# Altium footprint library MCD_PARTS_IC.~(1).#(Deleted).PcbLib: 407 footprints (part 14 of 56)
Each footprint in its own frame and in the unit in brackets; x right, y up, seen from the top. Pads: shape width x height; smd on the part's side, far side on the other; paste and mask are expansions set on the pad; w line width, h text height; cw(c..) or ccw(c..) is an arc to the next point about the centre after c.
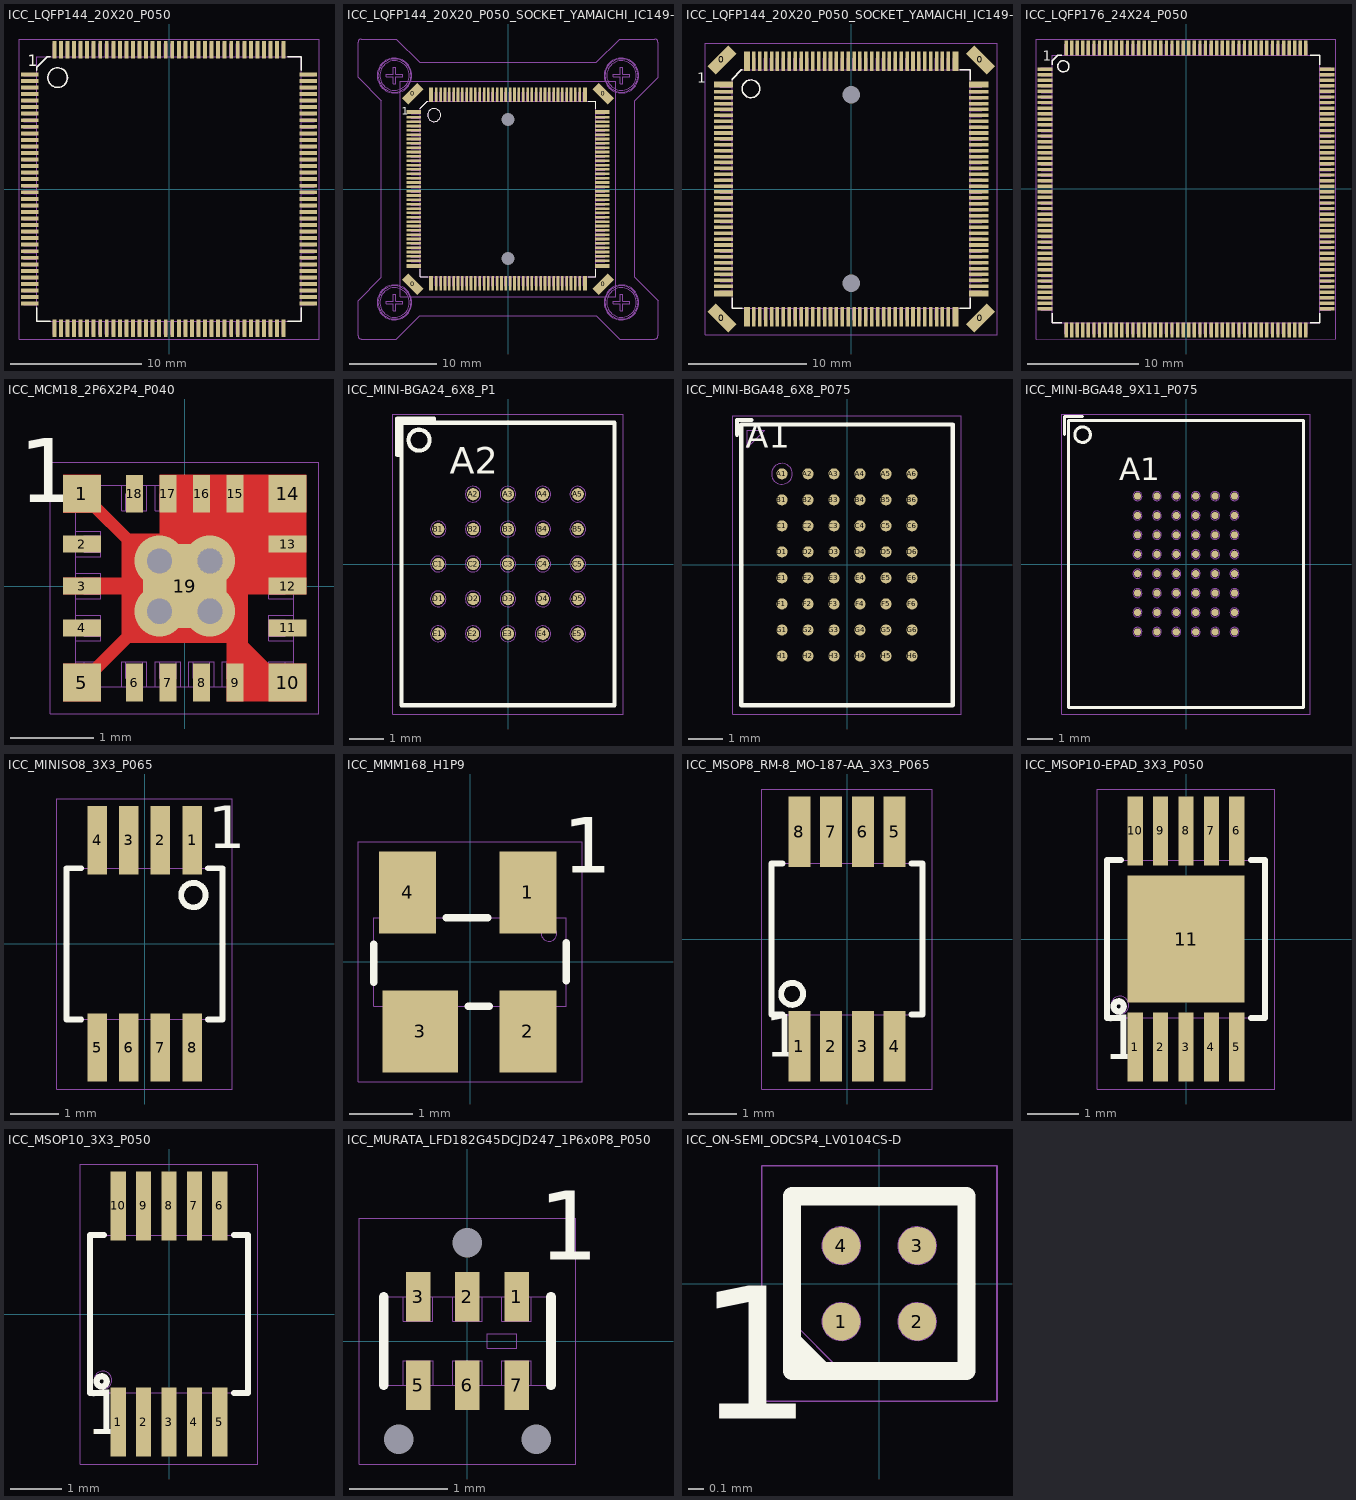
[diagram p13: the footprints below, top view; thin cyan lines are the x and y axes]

## ICC_LQFP144_20X20_P050 [mm]
height 1.6
pads (144):
  rect 1.35x0.3 smd mask+0.05: 1(-10.625,8.75) 2(-10.625,8.25) 3(-10.625,7.75) 4(-10.625,7.25) 5(-10.625,6.75) 6(-10.625,6.25) 7(-10.625,5.75) 8(-10.625,5.25) 9(-10.625,4.75) 10(-10.625,4.25) 11(-10.625,3.75) 12(-10.625,3.25) 13(-10.625,2.75) 14(-10.625,2.25) 15(-10.625,1.75) 16(-10.625,1.25) 17(-10.625,0.75) 18(-10.625,0.25) 19(-10.625,-0.25) 20(-10.625,-0.75) 21(-10.625,-1.25) 22(-10.625,-1.75) 23(-10.625,-2.25) 24(-10.625,-2.75) 25(-10.625,-3.25) 26(-10.625,-3.75) 27(-10.625,-4.25) 28(-10.625,-4.75) 29(-10.625,-5.25) 30(-10.625,-5.75) 31(-10.625,-6.25) 32(-10.625,-6.75) 33(-10.625,-7.25) 34(-10.625,-7.75) 35(-10.625,-8.25) 36(-10.625,-8.75) 73(10.625,-8.75) 74(10.625,-8.25) 75(10.625,-7.75) 76(10.625,-7.25) 77(10.625,-6.75) 78(10.625,-6.25) 79(10.625,-5.75) 80(10.625,-5.25) 81(10.625,-4.75) 82(10.625,-4.25) 83(10.625,-3.75) 84(10.625,-3.25) 85(10.625,-2.75) 86(10.625,-2.25) 87(10.625,-1.75) 88(10.625,-1.25) 89(10.625,-0.75) 90(10.625,-0.25) 91(10.625,0.25) 92(10.625,0.75) 93(10.625,1.25) 94(10.625,1.75) 95(10.625,2.25) 96(10.625,2.75) 97(10.625,3.25) 98(10.625,3.75) 99(10.625,4.25) 100(10.625,4.75) 101(10.625,5.25) 102(10.625,5.75) 103(10.625,6.25) 104(10.625,6.75) 105(10.625,7.25) 106(10.625,7.75) 107(10.625,8.25) 108(10.625,8.75)
  rect 0.3x1.35 smd mask+0.05: 37(-8.75,-10.625) 38(-8.25,-10.625) 39(-7.75,-10.625) 40(-7.25,-10.625) 41(-6.75,-10.625) 42(-6.25,-10.625) 43(-5.75,-10.625) 44(-5.25,-10.625) 45(-4.75,-10.625) 46(-4.25,-10.625) 47(-3.75,-10.625) 48(-3.25,-10.625) 49(-2.75,-10.625) 50(-2.25,-10.625) 51(-1.75,-10.625) 52(-1.25,-10.625) 53(-0.75,-10.625) 54(-0.25,-10.625) 55(0.25,-10.625) 56(0.75,-10.625) 57(1.25,-10.625) 58(1.75,-10.625) 59(2.25,-10.625) 60(2.75,-10.625) 61(3.25,-10.625) 62(3.75,-10.625) 63(4.25,-10.625) 64(4.75,-10.625) 65(5.25,-10.625) 66(5.75,-10.625) 67(6.25,-10.625) 68(6.75,-10.625) 69(7.25,-10.625) 70(7.75,-10.625) 71(8.25,-10.625) 72(8.75,-10.625) 109(8.75,10.625) 110(8.25,10.625) 111(7.75,10.625) 112(7.25,10.625) 113(6.75,10.625) 114(6.25,10.625) 115(5.75,10.625) 116(5.25,10.625) 117(4.75,10.625) 118(4.25,10.625) 119(3.75,10.625) 120(3.25,10.625) 121(2.75,10.625) 122(2.25,10.625) 123(1.75,10.625) 124(1.25,10.625) 125(0.75,10.625) 126(0.25,10.625) 127(-0.25,10.625) 128(-0.75,10.625) 129(-1.25,10.625) 130(-1.75,10.625) 131(-2.25,10.625) 132(-2.75,10.625) 133(-3.25,10.625) 134(-3.75,10.625) 135(-4.25,10.625) 136(-4.75,10.625) 137(-5.25,10.625) 138(-5.75,10.625) 139(-6.25,10.625) 140(-6.75,10.625) 141(-7.25,10.625) 142(-7.75,10.625) 143(-8.25,10.625) 144(-8.75,10.625)
Top Overlay:
  circle w0.12: c-8.5,8.5 r0.75
  lines w0.12: -10.1,-9.05 -10.1,-10.1 -9.05,-10.1 ; -10.1,9.05 -10.1,9.3 -9.3,10.1 -9.05,10.1 ; 9.05,-10.1 10.1,-10.1 10.1,-9.05 ; 9.05,10.1 10.1,10.1 10.1,9.05
  text "1" at -10.775,9.05 h1.5
M14-Top Assembly:
  drawing of 437 lines, arcs and shapes, not listed
  text "36" at -10,-9.25 h1
  text "37" at -9.725,-10 h1
  text "72" at 7.85,-10.025 h1
  text "73" at 8.05,-9.25 h1
  text "1" at -9.85,8.425 h1
  text "144" at -9.475,9.05 h1
  text "109" at 7.425,9.05 h1
  text "108" at 7.975,8.25 h1
  text "'.Designator'" at -2,-0.5 h0.75
M16-Top Courtyard:
  lines w0.01: -11.45,-11.45 -10.05,-11.45 11.45,-11.45 11.45,11.45 -9.05,11.45 -11.45,11.45 -11.45,-11.45
3D body: height 1.6, standoff 0, extent -10.099,-10.099 10.099,10.099
3D body "LQFP144_20X20_P050.STEP": height 1.58, standoff -0.02, extent -11,-11 11,11

## ICC_LQFP144_20X20_P050_SOCKET_YAMAICHI_IC149-144-145-B5 [mm]
height 12.6
pads (150):
  rect 1x2.5 smd rot 45 mask+0.05: 0(-10.96,-10.96) 0(10.96,10.96)
  rect 1x2.5 smd rot 135 mask+0.05: 0(-10.96,10.96) 0(10.96,-10.96)
  round 0 hole 1.5 unplated mask+0.05: 0(0,-8) 0(0,8)
  rect 1.65x0.5 smd mask+0.05: 1(-10.825,8.85) 36(-10.825,-8.85) 73(10.825,-8.85) 108(10.825,8.85)
  rect 1.65x0.3 smd mask+0.05: 2(-10.825,8.25) 3(-10.825,7.75) 4(-10.825,7.25) 5(-10.825,6.75) 6(-10.825,6.25) 7(-10.825,5.75) 8(-10.825,5.25) 9(-10.825,4.75) 10(-10.825,4.25) 11(-10.825,3.75) 12(-10.825,3.25) 13(-10.825,2.75) 14(-10.825,2.25) 15(-10.825,1.75) 16(-10.825,1.25) 17(-10.825,0.75) 18(-10.825,0.25) 19(-10.825,-0.25) 20(-10.825,-0.75) 21(-10.825,-1.25) 22(-10.825,-1.75) 23(-10.825,-2.25) 24(-10.825,-2.75) 25(-10.825,-3.25) 26(-10.825,-3.75) 27(-10.825,-4.25) 28(-10.825,-4.75) 29(-10.825,-5.25) 30(-10.825,-5.75) 31(-10.825,-6.25) 32(-10.825,-6.75) 33(-10.825,-7.25) 34(-10.825,-7.75) 35(-10.825,-8.25) 74(10.825,-8.25) 75(10.825,-7.75) 76(10.825,-7.25) 77(10.825,-6.75) 78(10.825,-6.25) 79(10.825,-5.75) 80(10.825,-5.25) 81(10.825,-4.75) 82(10.825,-4.25) 83(10.825,-3.75) 84(10.825,-3.25) 85(10.825,-2.75) 86(10.825,-2.25) 87(10.825,-1.75) 88(10.825,-1.25) 89(10.825,-0.75) 90(10.825,-0.25) 91(10.825,0.25) 92(10.825,0.75) 93(10.825,1.25) 94(10.825,1.75) 95(10.825,2.25) 96(10.825,2.75) 97(10.825,3.25) 98(10.825,3.75) 99(10.825,4.25) 100(10.825,4.75) 101(10.825,5.25) 102(10.825,5.75) 103(10.825,6.25) 104(10.825,6.75) 105(10.825,7.25) 106(10.825,7.75) 107(10.825,8.25)
  rect 0.5x1.65 smd mask+0.05: 37(-8.85,-10.825) 72(8.85,-10.825) 109(8.85,10.825) 144(-8.85,10.825)
  rect 0.3x1.65 smd mask+0.05: 38(-8.25,-10.825) 39(-7.75,-10.825) 40(-7.25,-10.825) 41(-6.75,-10.825) 42(-6.25,-10.825) 43(-5.75,-10.825) 44(-5.25,-10.825) 45(-4.75,-10.825) 46(-4.25,-10.825) 47(-3.75,-10.825) 48(-3.25,-10.825) 49(-2.75,-10.825) 50(-2.25,-10.825) 51(-1.75,-10.825) 52(-1.25,-10.825) 53(-0.75,-10.825) 54(-0.25,-10.825) 55(0.25,-10.825) 56(0.75,-10.825) 57(1.25,-10.825) 58(1.75,-10.825) 59(2.25,-10.825) 60(2.75,-10.825) 61(3.25,-10.825) 62(3.75,-10.825) 63(4.25,-10.825) 64(4.75,-10.825) 65(5.25,-10.825) 66(5.75,-10.825) 67(6.25,-10.825) 68(6.75,-10.825) 69(7.25,-10.825) 70(7.75,-10.825) 71(8.25,-10.825) 110(8.25,10.825) 111(7.75,10.825) 112(7.25,10.825) 113(6.75,10.825) 114(6.25,10.825) 115(5.75,10.825) 116(5.25,10.825) 117(4.75,10.825) 118(4.25,10.825) 119(3.75,10.825) 120(3.25,10.825) 121(2.75,10.825) 122(2.25,10.825) 123(1.75,10.825) 124(1.25,10.825) 125(0.75,10.825) 126(0.25,10.825) 127(-0.25,10.825) 128(-0.75,10.825) 129(-1.25,10.825) 130(-1.75,10.825) 131(-2.25,10.825) 132(-2.75,10.825) 133(-3.25,10.825) 134(-3.75,10.825) 135(-4.25,10.825) 136(-4.75,10.825) 137(-5.25,10.825) 138(-5.75,10.825) 139(-6.25,10.825) 140(-6.75,10.825) 141(-7.25,10.825) 142(-7.75,10.825) 143(-8.25,10.825)
Top Overlay:
  circle w0.12: c-8.5,8.5 r0.75
  lines w0.12: -10.1,-9.225 -10.1,-10.1 -9.225,-10.1 ; -10.1,9.225 -10.1,9.3 -9.3,10.1 -9.225,10.1 ; 9.225,-10.1 10.1,-10.1 10.1,-9.225 ; 9.225,10.1 10.1,10.1 10.1,9.225
  text "1" at -12.225,8.225 h1.5
M14-Top Assembly:
  drawing of 538 lines, arcs and shapes, not listed
  text "36" at -10,-9.25 h1
  text "37" at -9.725,-10 h1
  text "72" at 7.85,-10.025 h1
  text "73" at 8.05,-9.25 h1
  text "1" at -9.85,8.425 h1
  text "144" at -9.475,9.05 h1
  text "109" at 7.425,9.05 h1
  text "108" at 7.975,8.25 h1
  text "'.Designator'" at -2,-0.5 h0.75
M16-Top Courtyard:
  lines w0.01: -12.375,-12.375 -10.65,-12.375 12.375,-12.375 12.375,12.375 -8.125,12.375 -12.375,12.375 -12.375,-12.375
3D body: height 12.61, standoff 12.6, extent -15.05,-15.05 -11.05,-11.05
3D body: height 12.61, standoff 12.6, extent 11.05,-15.05 15.05,-11.05
3D body: height 12.61, standoff 12.6, extent 11.05,11.05 15.05,15.05
3D body: height 12.61, standoff 12.6, extent -15.05,11.05 -11.05,15.05
3D body: height 12.6, standoff 3.5, extent 10.5,-10.15 14.55,10.15
3D body: height 12.6, standoff 3.5, extent -10.15,10.5 10.15,14.55
3D body: height 12.6, standoff 3.5, extent -14.55,-10.15 -10.5,10.15
3D body: height 12.6, standoff 3.5, extent -10.15,-14.55 10.15,-10.5
3D body: height 3.5, standoff 0, extent -12.188,-12.187 -9.75,-9.75
3D body: height 3.5, standoff 0, extent 9.738,-12.175 12.175,-9.737
3D body: height 3.5, standoff 0, extent 9.744,9.744 12.181,12.181
3D body: height 3.5, standoff 0, extent -12.175,9.737 -9.738,12.175
3D body: height 3.5, standoff 0, extent -10.5,-10.5 10.5,10.5
3D body "LQFP144_20X20_P050.STEP": height 4.97, standoff 3.37, extent -11,-11 11,11
3D body: height 12.6, standoff 3.5, extent -17.25,10.15 -10.15,17.25
3D body: height 12.6, standoff 3.5, extent 10.15,10.15 17.25,17.25
3D body: height 12.6, standoff 3.5, extent 10.15,-17.25 17.25,-10.15
3D body: height 12.6, standoff 3.5, extent -17.25,-17.25 -10.15,-10.15
3D body: height 0.2, standoff 0, extent -11.1,8.65 -10.5,8.85
3D body: height 0.2, standoff 0, extent -11.1,8.15 -10.5,8.35
3D body: height 0.2, standoff 0, extent -11.1,7.65 -10.5,7.85
3D body: height 0.2, standoff 0, extent -11.1,7.15 -10.5,7.35
3D body: height 0.2, standoff 0, extent -11.1,6.65 -10.5,6.85
3D body: height 0.2, standoff 0, extent -11.1,6.15 -10.5,6.35
3D body: height 0.2, standoff 0, extent -11.1,3.15 -10.5,3.35
3D body: height 0.2, standoff 0, extent -11.1,3.65 -10.5,3.85
3D body: height 0.2, standoff 0, extent -11.1,4.15 -10.5,4.35
3D body: height 0.2, standoff 0, extent -11.1,4.65 -10.5,4.85
3D body: height 0.2, standoff 0, extent -11.1,5.15 -10.5,5.35
3D body: height 0.2, standoff 0, extent -11.1,5.65 -10.5,5.85
3D body: height 0.2, standoff 0, extent -11.1,0.15 -10.5,0.35
3D body: height 0.2, standoff 0, extent -11.1,0.65 -10.5,0.85
3D body: height 0.2, standoff 0, extent -11.1,1.15 -10.5,1.35
3D body: height 0.2, standoff 0, extent -11.1,1.65 -10.5,1.85
3D body: height 0.2, standoff 0, extent -11.1,2.15 -10.5,2.35
3D body: height 0.2, standoff 0, extent -11.1,2.65 -10.5,2.85
3D body: height 0.2, standoff 0, extent -11.1,-0.35 -10.5,-0.15
3D body: height 0.2, standoff 0, extent -11.1,-0.85 -10.5,-0.65
3D body: height 0.2, standoff 0, extent -11.1,-1.35 -10.5,-1.15
3D body: height 0.2, standoff 0, extent -11.1,-1.85 -10.5,-1.65
3D body: height 0.2, standoff 0, extent -11.1,-2.35 -10.5,-2.15
3D body: height 0.2, standoff 0, extent -11.1,-2.85 -10.5,-2.65
3D body: height 0.2, standoff 0, extent -11.1,-5.85 -10.5,-5.65
3D body: height 0.2, standoff 0, extent -11.1,-5.35 -10.5,-5.15
3D body: height 0.2, standoff 0, extent -11.1,-4.85 -10.5,-4.65
3D body: height 0.2, standoff 0, extent -11.1,-4.35 -10.5,-4.15
3D body: height 0.2, standoff 0, extent -11.1,-3.85 -10.5,-3.65
3D body: height 0.2, standoff 0, extent -11.1,-3.35 -10.5,-3.15
3D body: height 0.2, standoff 0, extent -11.1,-6.35 -10.5,-6.15
3D body: height 0.2, standoff 0, extent -11.1,-6.85 -10.5,-6.65
3D body: height 0.2, standoff 0, extent -11.1,-7.35 -10.5,-7.15
3D body: height 0.2, standoff 0, extent -11.1,-7.85 -10.5,-7.65
3D body: height 0.2, standoff 0, extent -11.1,-8.35 -10.5,-8.15
3D body: height 0.2, standoff 0, extent -11.1,-8.85 -10.5,-8.65
3D body: height 0.2, standoff 0, extent 8.65,-11.1 8.85,-10.5
3D body: height 0.2, standoff 0, extent 8.15,-11.1 8.35,-10.5
3D body: height 0.2, standoff 0, extent 7.65,-11.1 7.85,-10.5
3D body: height 0.2, standoff 0, extent 7.15,-11.1 7.35,-10.5
3D body: height 0.2, standoff 0, extent 6.65,-11.1 6.85,-10.5
3D body: height 0.2, standoff 0, extent 6.15,-11.1 6.35,-10.5
3D body: height 0.2, standoff 0, extent 3.15,-11.1 3.35,-10.5
3D body: height 0.2, standoff 0, extent 3.65,-11.1 3.85,-10.5
3D body: height 0.2, standoff 0, extent 4.15,-11.1 4.35,-10.5
3D body: height 0.2, standoff 0, extent 4.65,-11.1 4.85,-10.5
3D body: height 0.2, standoff 0, extent 5.15,-11.1 5.35,-10.5
3D body: height 0.2, standoff 0, extent 5.65,-11.1 5.85,-10.5
3D body: height 0.2, standoff 0, extent 2.65,-11.1 2.85,-10.5
3D body: height 0.2, standoff 0, extent 2.15,-11.1 2.35,-10.5
3D body: height 0.2, standoff 0, extent 1.65,-11.1 1.85,-10.5
3D body: height 0.2, standoff 0, extent 1.15,-11.1 1.35,-10.5
3D body: height 0.2, standoff 0, extent 0.65,-11.1 0.85,-10.5
3D body: height 0.2, standoff 0, extent 0.15,-11.1 0.35,-10.5
3D body: height 0.2, standoff 0, extent -2.85,-11.1 -2.65,-10.5
3D body: height 0.2, standoff 0, extent -2.35,-11.1 -2.15,-10.5
3D body: height 0.2, standoff 0, extent -1.85,-11.1 -1.65,-10.5
3D body: height 0.2, standoff 0, extent -1.35,-11.1 -1.15,-10.5
3D body: height 0.2, standoff 0, extent -0.85,-11.1 -0.65,-10.5
3D body: height 0.2, standoff 0, extent -0.35,-11.1 -0.15,-10.5
3D body: height 0.2, standoff 0, extent -5.85,-11.1 -5.65,-10.5
3D body: height 0.2, standoff 0, extent -5.35,-11.1 -5.15,-10.5
3D body: height 0.2, standoff 0, extent -4.85,-11.1 -4.65,-10.5
3D body: height 0.2, standoff 0, extent -4.35,-11.1 -4.15,-10.5
3D body: height 0.2, standoff 0, extent -3.85,-11.1 -3.65,-10.5
3D body: height 0.2, standoff 0, extent -3.35,-11.1 -3.15,-10.5
3D body: height 0.2, standoff 0, extent -6.35,-11.1 -6.15,-10.5
3D body: height 0.2, standoff 0, extent -6.85,-11.1 -6.65,-10.5
3D body: height 0.2, standoff 0, extent -7.35,-11.1 -7.15,-10.5
3D body: height 0.2, standoff 0, extent -7.85,-11.1 -7.65,-10.5
3D body: height 0.2, standoff 0, extent -8.35,-11.1 -8.15,-10.5
3D body: height 0.2, standoff 0, extent -8.85,-11.1 -8.65,-10.5
3D body: height 0.2, standoff 0, extent 10.5,8.65 11.1,8.85
3D body: height 0.2, standoff 0, extent 10.5,8.15 11.1,8.35
3D body: height 0.2, standoff 0, extent 10.5,7.65 11.1,7.85
3D body: height 0.2, standoff 0, extent 10.5,7.15 11.1,7.35
3D body: height 0.2, standoff 0, extent 10.5,6.65 11.1,6.85
3D body: height 0.2, standoff 0, extent 10.5,6.15 11.1,6.35
3D body: height 0.2, standoff 0, extent 10.5,3.15 11.1,3.35
3D body: height 0.2, standoff 0, extent 10.5,3.65 11.1,3.85
3D body: height 0.2, standoff 0, extent 10.5,4.15 11.1,4.35
3D body: height 0.2, standoff 0, extent 10.5,4.65 11.1,4.85
3D body: height 0.2, standoff 0, extent 10.5,5.15 11.1,5.35
3D body: height 0.2, standoff 0, extent 10.5,5.65 11.1,5.85
3D body: height 0.2, standoff 0, extent 10.5,2.65 11.1,2.85
3D body: height 0.2, standoff 0, extent 10.5,2.15 11.1,2.35
3D body: height 0.2, standoff 0, extent 10.5,1.65 11.1,1.85
3D body: height 0.2, standoff 0, extent 10.5,1.15 11.1,1.35
3D body: height 0.2, standoff 0, extent 10.5,0.65 11.1,0.85
3D body: height 0.2, standoff 0, extent 10.5,0.15 11.1,0.35
3D body: height 0.2, standoff 0, extent 10.5,-2.85 11.1,-2.65
3D body: height 0.2, standoff 0, extent 10.5,-2.35 11.1,-2.15
3D body: height 0.2, standoff 0, extent 10.5,-1.85 11.1,-1.65
3D body: height 0.2, standoff 0, extent 10.5,-1.35 11.1,-1.15
3D body: height 0.2, standoff 0, extent 10.5,-0.85 11.1,-0.65
3D body: height 0.2, standoff 0, extent 10.5,-0.35 11.1,-0.15
3D body: height 0.2, standoff 0, extent 10.5,-5.85 11.1,-5.65
3D body: height 0.2, standoff 0, extent 10.5,-5.35 11.1,-5.15
3D body: height 0.2, standoff 0, extent 10.5,-4.85 11.1,-4.65
3D body: height 0.2, standoff 0, extent 10.5,-4.35 11.1,-4.15
3D body: height 0.2, standoff 0, extent 10.5,-3.85 11.1,-3.65
3D body: height 0.2, standoff 0, extent 10.5,-3.35 11.1,-3.15
3D body: height 0.2, standoff 0, extent 10.5,-6.35 11.1,-6.15
3D body: height 0.2, standoff 0, extent 10.5,-6.85 11.1,-6.65
3D body: height 0.2, standoff 0, extent 10.5,-7.35 11.1,-7.15
3D body: height 0.2, standoff 0, extent 10.5,-7.85 11.1,-7.65
3D body: height 0.2, standoff 0, extent 10.5,-8.35 11.1,-8.15
3D body: height 0.2, standoff 0, extent 10.5,-8.85 11.1,-8.65
3D body: height 0.2, standoff 0, extent -8.85,10.5 -8.65,11.1
3D body: height 0.2, standoff 0, extent -8.35,10.5 -8.15,11.1
3D body: height 0.2, standoff 0, extent -7.85,10.5 -7.65,11.1
3D body: height 0.2, standoff 0, extent -7.35,10.5 -7.15,11.1
3D body: height 0.2, standoff 0, extent -6.85,10.5 -6.65,11.1
3D body: height 0.2, standoff 0, extent -6.35,10.5 -6.15,11.1
3D body: height 0.2, standoff 0, extent -3.35,10.5 -3.15,11.1
3D body: height 0.2, standoff 0, extent -3.85,10.5 -3.65,11.1
3D body: height 0.2, standoff 0, extent -4.35,10.5 -4.15,11.1
3D body: height 0.2, standoff 0, extent -4.85,10.5 -4.65,11.1
3D body: height 0.2, standoff 0, extent -5.35,10.5 -5.15,11.1
3D body: height 0.2, standoff 0, extent -5.85,10.5 -5.65,11.1
3D body: height 0.2, standoff 0, extent -2.85,10.5 -2.65,11.1
3D body: height 0.2, standoff 0, extent -2.35,10.5 -2.15,11.1
3D body: height 0.2, standoff 0, extent -1.85,10.5 -1.65,11.1
3D body: height 0.2, standoff 0, extent -1.35,10.5 -1.15,11.1
3D body: height 0.2, standoff 0, extent -0.85,10.5 -0.65,11.1
3D body: height 0.2, standoff 0, extent -0.35,10.5 -0.15,11.1
3D body: height 0.2, standoff 0, extent 2.65,10.5 2.85,11.1
3D body: height 0.2, standoff 0, extent 2.15,10.5 2.35,11.1
3D body: height 0.2, standoff 0, extent 1.65,10.5 1.85,11.1
3D body: height 0.2, standoff 0, extent 1.15,10.5 1.35,11.1
3D body: height 0.2, standoff 0, extent 0.65,10.5 0.85,11.1
3D body: height 0.2, standoff 0, extent 0.15,10.5 0.35,11.1
3D body: height 0.2, standoff 0, extent 5.65,10.5 5.85,11.1
3D body: height 0.2, standoff 0, extent 5.15,10.5 5.35,11.1
3D body: height 0.2, standoff 0, extent 4.65,10.5 4.85,11.1
3D body: height 0.2, standoff 0, extent 4.15,10.5 4.35,11.1
3D body: height 0.2, standoff 0, extent 3.65,10.5 3.85,11.1
3D body: height 0.2, standoff 0, extent 3.15,10.5 3.35,11.1
3D body: height 0.2, standoff 0, extent 6.15,10.5 6.35,11.1
3D body: height 0.2, standoff 0, extent 6.65,10.5 6.85,11.1
3D body: height 0.2, standoff 0, extent 7.15,10.5 7.35,11.1
3D body: height 0.2, standoff 0, extent 7.65,10.5 7.85,11.1
3D body: height 0.2, standoff 0, extent 8.15,10.5 8.35,11.1
3D body: height 0.2, standoff 0, extent 8.65,10.5 8.85,11.1

## ICC_LQFP144_20X20_P050_SOCKET_YAMAICHI_IC149-144-145-B5_NM [mm]
height 1.6
pads (150):
  rect 1x2.5 smd rot 45 mask+0.05: 0(-10.96,-10.96) 0(10.96,10.96)
  rect 1x2.5 smd rot 135 mask+0.05: 0(-10.96,10.96) 0(10.96,-10.96)
  round 0 hole 1.5 unplated mask+0.05: 0(0,-8) 0(0,8)
  rect 1.65x0.5 smd mask+0.05: 1(-10.825,8.85) 36(-10.825,-8.85) 73(10.825,-8.85) 108(10.825,8.85)
  rect 1.65x0.3 smd mask+0.05: 2(-10.825,8.25) 3(-10.825,7.75) 4(-10.825,7.25) 5(-10.825,6.75) 6(-10.825,6.25) 7(-10.825,5.75) 8(-10.825,5.25) 9(-10.825,4.75) 10(-10.825,4.25) 11(-10.825,3.75) 12(-10.825,3.25) 13(-10.825,2.75) 14(-10.825,2.25) 15(-10.825,1.75) 16(-10.825,1.25) 17(-10.825,0.75) 18(-10.825,0.25) 19(-10.825,-0.25) 20(-10.825,-0.75) 21(-10.825,-1.25) 22(-10.825,-1.75) 23(-10.825,-2.25) 24(-10.825,-2.75) 25(-10.825,-3.25) 26(-10.825,-3.75) 27(-10.825,-4.25) 28(-10.825,-4.75) 29(-10.825,-5.25) 30(-10.825,-5.75) 31(-10.825,-6.25) 32(-10.825,-6.75) 33(-10.825,-7.25) 34(-10.825,-7.75) 35(-10.825,-8.25) 74(10.825,-8.25) 75(10.825,-7.75) 76(10.825,-7.25) 77(10.825,-6.75) 78(10.825,-6.25) 79(10.825,-5.75) 80(10.825,-5.25) 81(10.825,-4.75) 82(10.825,-4.25) 83(10.825,-3.75) 84(10.825,-3.25) 85(10.825,-2.75) 86(10.825,-2.25) 87(10.825,-1.75) 88(10.825,-1.25) 89(10.825,-0.75) 90(10.825,-0.25) 91(10.825,0.25) 92(10.825,0.75) 93(10.825,1.25) 94(10.825,1.75) 95(10.825,2.25) 96(10.825,2.75) 97(10.825,3.25) 98(10.825,3.75) 99(10.825,4.25) 100(10.825,4.75) 101(10.825,5.25) 102(10.825,5.75) 103(10.825,6.25) 104(10.825,6.75) 105(10.825,7.25) 106(10.825,7.75) 107(10.825,8.25)
  rect 0.5x1.65 smd mask+0.05: 37(-8.85,-10.825) 72(8.85,-10.825) 109(8.85,10.825) 144(-8.85,10.825)
  rect 0.3x1.65 smd mask+0.05: 38(-8.25,-10.825) 39(-7.75,-10.825) 40(-7.25,-10.825) 41(-6.75,-10.825) 42(-6.25,-10.825) 43(-5.75,-10.825) 44(-5.25,-10.825) 45(-4.75,-10.825) 46(-4.25,-10.825) 47(-3.75,-10.825) 48(-3.25,-10.825) 49(-2.75,-10.825) 50(-2.25,-10.825) 51(-1.75,-10.825) 52(-1.25,-10.825) 53(-0.75,-10.825) 54(-0.25,-10.825) 55(0.25,-10.825) 56(0.75,-10.825) 57(1.25,-10.825) 58(1.75,-10.825) 59(2.25,-10.825) 60(2.75,-10.825) 61(3.25,-10.825) 62(3.75,-10.825) 63(4.25,-10.825) 64(4.75,-10.825) 65(5.25,-10.825) 66(5.75,-10.825) 67(6.25,-10.825) 68(6.75,-10.825) 69(7.25,-10.825) 70(7.75,-10.825) 71(8.25,-10.825) 110(8.25,10.825) 111(7.75,10.825) 112(7.25,10.825) 113(6.75,10.825) 114(6.25,10.825) 115(5.75,10.825) 116(5.25,10.825) 117(4.75,10.825) 118(4.25,10.825) 119(3.75,10.825) 120(3.25,10.825) 121(2.75,10.825) 122(2.25,10.825) 123(1.75,10.825) 124(1.25,10.825) 125(0.75,10.825) 126(0.25,10.825) 127(-0.25,10.825) 128(-0.75,10.825) 129(-1.25,10.825) 130(-1.75,10.825) 131(-2.25,10.825) 132(-2.75,10.825) 133(-3.25,10.825) 134(-3.75,10.825) 135(-4.25,10.825) 136(-4.75,10.825) 137(-5.25,10.825) 138(-5.75,10.825) 139(-6.25,10.825) 140(-6.75,10.825) 141(-7.25,10.825) 142(-7.75,10.825) 143(-8.25,10.825)
Top Overlay:
  circle w0.12: c-8.5,8.5 r0.75
  lines w0.12: -10.1,-9.225 -10.1,-10.1 -9.225,-10.1 ; -10.1,9.225 -10.1,9.3 -9.3,10.1 -9.225,10.1 ; 9.225,-10.1 10.1,-10.1 10.1,-9.225 ; 9.225,10.1 10.1,10.1 10.1,9.225
  text "1" at -13.075,8.725 h1.5
M14-Top Assembly:
  drawing of 438 lines, arcs and shapes, not listed
  text "36" at -9.8,-9.05 h1
  text "37" at -9.775,-9.85 h1
  text "72" at 7.825,-9.825 h1
  text "73" at 7.775,-9.175 h1
  text "1" at -9.85,8.425 h1
  text "144" at -9.225,8.825 h1
  text "109" at 7.2,8.725 h1
  text "108" at 7.85,8 h1
  text "'.Designator'" at -2,-0.5 h0.75
M16-Top Courtyard:
  lines w0.01: -12.375,-12.375 -10.65,-12.375 12.375,-12.375 12.375,12.375 -8.125,12.375 -12.375,12.375 -12.375,-12.375
3D body "LQFP144_20X20_P050.STEP": height 1.6, standoff 0, extent -11,-11 11,11

## ICC_LQFP176_24X24_P050 [mm] "MCD-04398"
height 1.6
pads (176):
  rect 1.35x0.3 smd mask+0.05: 1(-12.625,10.75) 2(-12.625,10.25) 3(-12.625,9.75) 4(-12.625,9.25) 5(-12.625,8.75) 6(-12.625,8.25) 7(-12.625,7.75) 8(-12.625,7.25) 9(-12.625,6.75) 10(-12.625,6.25) 11(-12.625,5.75) 12(-12.625,5.25) 13(-12.625,4.75) 14(-12.625,4.25) 15(-12.625,3.75) 16(-12.625,3.25) 17(-12.625,2.75) 18(-12.625,2.25) 19(-12.625,1.75) 20(-12.625,1.25) 21(-12.625,0.75) 22(-12.625,0.25) 23(-12.625,-0.25) 24(-12.625,-0.75) 25(-12.625,-1.25) 26(-12.625,-1.75) 27(-12.625,-2.25) 28(-12.625,-2.75) 29(-12.625,-3.25) 30(-12.625,-3.75) 31(-12.625,-4.25) 32(-12.625,-4.75) 33(-12.625,-5.25) 34(-12.625,-5.75) 35(-12.625,-6.25) 36(-12.625,-6.75) 37(-12.625,-7.25) 38(-12.625,-7.75) 39(-12.625,-8.25) 40(-12.625,-8.75) 41(-12.625,-9.25) 42(-12.625,-9.75) 43(-12.625,-10.25) 44(-12.625,-10.75) 89(12.625,-10.75) 90(12.625,-10.25) 91(12.625,-9.75) 92(12.625,-9.25) 93(12.625,-8.75) 94(12.625,-8.25) 95(12.625,-7.75) 96(12.625,-7.25) 97(12.625,-6.75) 98(12.625,-6.25) 99(12.625,-5.75) 100(12.625,-5.25) 101(12.625,-4.75) 102(12.625,-4.25) 103(12.625,-3.75) 104(12.625,-3.25) 105(12.625,-2.75) 106(12.625,-2.25) 107(12.625,-1.75) 108(12.625,-1.25) 109(12.625,-0.75) 110(12.625,-0.25) 111(12.625,0.25) 112(12.625,0.75) 113(12.625,1.25) 114(12.625,1.75) 115(12.625,2.25) 116(12.625,2.75) 117(12.625,3.25) 118(12.625,3.75) 119(12.625,4.25) 120(12.625,4.75) 121(12.625,5.25) 122(12.625,5.75) 123(12.625,6.25) 124(12.625,6.75) 125(12.625,7.25) 126(12.625,7.75) 127(12.625,8.25) 128(12.625,8.75) 129(12.625,9.25) 130(12.625,9.75) 131(12.625,10.25) 132(12.625,10.75)
  rect 0.3x1.35 smd mask+0.05: 45(-10.75,-12.625) 46(-10.25,-12.625) 47(-9.75,-12.625) 48(-9.25,-12.625) 49(-8.75,-12.625) 50(-8.25,-12.625) 51(-7.75,-12.625) 52(-7.25,-12.625) 53(-6.75,-12.625) 54(-6.25,-12.625) 55(-5.75,-12.625) 56(-5.25,-12.625) 57(-4.75,-12.625) 58(-4.25,-12.625) 59(-3.75,-12.625) 60(-3.25,-12.625) 61(-2.75,-12.625) 62(-2.25,-12.625) 63(-1.75,-12.625) 64(-1.25,-12.625) 65(-0.75,-12.625) 66(-0.25,-12.625) 67(0.25,-12.625) 68(0.75,-12.625) 69(1.25,-12.625) 70(1.75,-12.625) 71(2.25,-12.625) 72(2.75,-12.625) 73(3.25,-12.625) 74(3.75,-12.625) 75(4.25,-12.625) 76(4.75,-12.625) 77(5.25,-12.625) 78(5.75,-12.625) 79(6.25,-12.625) 80(6.75,-12.625) 81(7.25,-12.625) 82(7.75,-12.625) 83(8.25,-12.625) 84(8.75,-12.625) 85(9.25,-12.625) 86(9.75,-12.625) 87(10.25,-12.625) 88(10.75,-12.625) 133(10.75,12.625) 134(10.25,12.625) 135(9.75,12.625) 136(9.25,12.625) 137(8.75,12.625) 138(8.25,12.625) 139(7.75,12.625) 140(7.25,12.625) 141(6.75,12.625) 142(6.25,12.625) 143(5.75,12.625) 144(5.25,12.625) 145(4.75,12.625) 146(4.25,12.625) 147(3.75,12.625) 148(3.25,12.625) 149(2.75,12.625) 150(2.25,12.625) 151(1.75,12.625) 152(1.25,12.625) 153(0.75,12.625) 154(0.25,12.625) 155(-0.25,12.625) 156(-0.75,12.625) 157(-1.25,12.625) 158(-1.75,12.625) 159(-2.25,12.625) 160(-2.75,12.625) 161(-3.25,12.625) 162(-3.75,12.625) 163(-4.25,12.625) 164(-4.75,12.625) 165(-5.25,12.625) 166(-5.75,12.625) 167(-6.25,12.625) 168(-6.75,12.625) 169(-7.25,12.625) 170(-7.75,12.625) 171(-8.25,12.625) 172(-8.75,12.625) 173(-9.25,12.625) 174(-9.75,12.625) 175(-10.25,12.625) 176(-10.75,12.625)
Top Overlay:
  circle w0.12: c-11,11 r0.5
  lines w0.12: -12,-11.127 -12,-12 -11.125,-12 ; -12,11.125 -12,11.5 -11.5,12 -11.125,12 ; 11.125,12 12,12 12,11.127 ; 11.127,-12 12,-12 12,-11.125
  text "1" at -12.85,11.175 h1.5
M14-Top Assembly:
  drawing of 533 lines, arcs and shapes, not listed
  text "44" at -12.975,-11.125 h1
  text "88" at 9.8,-12.85 h1
  text "45" at -11.8,-12.825 h1
  text "176" at -12.05,12 h1
  text "1" at -12.625,10.45 h1
  text "132" at 11.85,10.175 h1
  text "133" at 8.625,11.85 h1
  text "89" at 11.025,-11.275 h1
  text "'.Designator'" at -2,-0.5 h0.75
M16-Top Courtyard:
  lines w0.01: -13.45,-13.45 13.45,-13.45 13.45,13.45 -13.45,13.45 -13.45,-13.45
3D body "User Library-LQFP176-0_5.STEP": height 1.6, standoff 0.03, extent -12.886,-12.886 12.886,12.886

## ICC_MCM18_2P6X2P4_P040 [mm]
height 0.8
pads (19):
  rect 0.45x0.45 smd mask+0.05: 1(-1.225,1.1) 5(-1.225,-1.15) 10(1.225,-1.15) 14(1.225,1.1)
  rect 0.45x0.2 smd mask+0.05: 2(-1.225,0.5) 3(-1.225,0) 4(-1.225,-0.5) 11(1.225,-0.5) 12(1.225,0) 13(1.225,0.5)
  rect 0.2x0.45 smd mask+0.05: 6(-0.6,-1.15) 7(-0.2,-1.15) 8(0.2,-1.15) 9(0.6,-1.15) 15(0.6,1.1) 16(0.2,1.1) 17(-0.2,1.1) 18(-0.6,1.1)
  rect 1x1 smd mask+0.05: 19(0,0)
via 0.3,0.3 diameter 0.6 hole 0.3
via 0.3,-0.3 diameter 0.6 hole 0.3
via -0.3,-0.3 diameter 0.6 hole 0.3
via -0.3,0.3 diameter 0.6 hole 0.3
Top Layer:
  region: -0.3,0.625 -0.65,0.625 -1,0.975 -1,1.325 -1.45,1.325 -1.45,0.875 -1.1,0.875 -0.75,0.525 -0.75,0.1 -1.45,0.1 -1.45,-0.1 -0.75,-0.1 -0.75,-0.575 -1.1,-0.925 -1.45,-0.925 -1.45,-1.375 -1,-1.375 -1,-1.05 -1,-1.025 -0.65,-0.675 0.5,-0.675 0.5,-1.375 1.45,-1.375 1.45,-0.925 1,-0.925 0.75,-0.675 0.75,-0.1 1.45,-0.1 1.45,1.325 -0.3,1.325
Top Overlay:
  text "1" at -1.975,0.75 h1.3
M14-Top Assembly:
  lines w0.01: -1.3,-0.9 -1,-0.9 -1,-1.2 ; -1.3,-0.65 -1,-0.65 -1,-0.35 -1.3,-0.35 ; -1.3,-0.15 -1,-0.15 -1,0.15 -1.3,0.15 ; -1.3,0.35 -1,0.35 -1,0.65 -1.3,0.65 ; -1.3,0.9 -1,0.9 -1,1.2 ; -1.2,-0.9 -1.2,-1.1 -1,-1.1 ; -1.2,0.9 -1.2,1.1 -1,1.1 ; -1,-0.6 -1.2,-0.6 -1.2,-0.4 -1,-0.4 ; -1,-0.1 -1.2,-0.1 -1.2,0.1 -1,0.1 ; -1,0.4 -1.2,0.4 -1.2,0.6 -1,0.6 ; -0.75,-1.2 -0.75,-0.9 -0.45,-0.9 -0.45,-1.2 ; -0.75,1.2 -0.75,0.9 -0.45,0.9 -0.45,1.2 ; -0.7,-0.9 -0.7,-1.1 -0.5,-1.1 -0.5,-0.9 ; -0.7,0.9 -0.7,1.1 -0.5,1.1 -0.5,0.9 ; -0.35,-1.2 -0.35,-0.9 -0.05,-0.9 -0.05,-1.2 ; -0.35,1.2 -0.35,0.9 -0.05,0.9 -0.05,1.2 ; -0.3,-0.9 -0.3,-1.1 -0.1,-1.1 -0.1,-0.9 ; -0.3,0.9 -0.3,1.1 -0.1,1.1 -0.1,0.9 ; 0.05,-1.2 0.05,-0.9 0.35,-0.9 0.35,-1.2 ; 0.05,1.2 0.05,0.9 0.35,0.9 0.35,1.2 ; 0.1,-0.9 0.1,-1.1 0.3,-1.1 0.3,-0.9 ; 0.1,0.9 0.1,1.1 0.3,1.1 0.3,0.9 ; 0.45,-1.2 0.45,-0.9 0.75,-0.9 0.75,-1.2 ; 0.45,1.2 0.45,0.9 0.75,0.9 0.75,1.2 ; 0.5,-0.9 0.5,-1.1 0.7,-1.1 0.7,-0.9 ; 0.5,0.9 0.5,1.1 0.7,1.1 0.7,0.9 ; 1,-1.2 1,-0.9 1.3,-0.9 ; 1,-1.1 1.2,-1.1 1.2,-0.9 ; 1,-0.6 1.2,-0.6 1.2,-0.4 1,-0.4 ; 1,-0.1 1.2,-0.1 1.2,0.1 1,0.1 ; 1,0.4 1.2,0.4 1.2,0.6 1,0.6 ; 1,1.1 1.2,1.1 1.2,0.9 ; 1,1.2 1,0.9 1.3,0.9 ; 1.3,-0.65 1,-0.65 1,-0.35 1.3,-0.35 ; 1.3,-0.15 1,-0.15 1,0.15 1.3,0.15 ; 1.3,0.35 1,0.35 1,0.65 1.3,0.65 ; -1.3,-1.2 1.3,-1.2 1.3,1.2 -1.3,1.2 -1.3,-1.2 ; -0.5,-0.5 0.5,-0.5 0.5,0.5 -0.3,0.5 -0.5,0.3 -0.5,-0.5
  text "1" at -1.2,0.9 h0.5
  text "'.Designator'" at -2,-0.5 h0.75
  text "5" at -1.2,-1.2 h0.5
  text "10" at 0.925,-1.2 h0.5
  text "14" at 0.925,0.9 h0.5
M16-Top Courtyard:
  lines w0.01: -1.6,-1.525 1.6,-1.525 1.6,1.475 -1.6,1.475 -1.6,-1.525
3D body: height 0.8, standoff 0, extent -1.3,-1.2 1.3,1.2
3D body: height 0.81, standoff 0.8, extent -1.125,0.725 -0.825,1.025

## ICC_MINI-BGA24_6X8_P1 [mm] "MCD-01391"
height 1.2
pads (24):
  round 0.35 smd mask+0.05: A2(-1,2) A3(0,2) A4(1,2) A5(2,2) B1(-2,1) B2(-1,1) B3(0,1) B4(1,1) B5(2,1) C1(-2,0) C2(-1,0) C3(0,0) C4(1,0) C5(2,0) D1(-2,-1) D2(-1,-1) D3(0,-1) D4(1,-1) D5(2,-1) E1(-2,-2) E2(-1,-2) E3(0,-2) E4(1,-2) E5(2,-2)
Top Overlay:
  circle w0.12: c-2.55,3.55 r0.3
  lines w0.12: -3.15,3.125 -3.15,4.15 -2.125,4.15 ; -3.05,3.125 -3.175,3.125 -3.175,4.175 -2.125,4.175 -2.125,4.05 ; -3.05,-4.05 -3.05,4.05 3.05,4.05 3.05,-4.05 -3.05,-4.05
  text "A2" at -1.675,2.325 h1.3
M14-Top Assembly:
  circle w0.01: c-2,-2 r0.225
  circle w0.01: c-1,-2 r0.225
  circle w0.01: c0,-2 r0.225
  circle w0.01: c1,-2 r0.225
  circle w0.01: c2,-2 r0.225
  circle w0.01: c-2,-1 r0.225
  circle w0.01: c-1,-1 r0.225
  circle w0.01: c0,-1 r0.225
  circle w0.01: c1,-1 r0.225
  circle w0.01: c2,-1 r0.225
  circle w0.01: c-2,0 r0.225
  circle w0.01: c-1,0 r0.225
  circle w0.01: c0,0 r0.225
  circle w0.01: c1,0 r0.225
  circle w0.01: c2,0 r0.225
  circle w0.01: c-2,1 r0.225
  circle w0.01: c-1,1 r0.225
  circle w0.01: c0,1 r0.225
  circle w0.01: c1,1 r0.225
  circle w0.01: c2,1 r0.225
  circle w0.01: c2,2 r0.225
  circle w0.01: c1,2 r0.225
  circle w0.01: c0,2 r0.225
  circle w0.01: c-1,2 r0.225
  circle w0.01: c-2.55,3.55 r0.325
  lines w0.01: -3.05,-4.05 3.05,-4.05 3.05,4.05 -3.05,4.05 -3.05,-4.05
  text "A2" at -1.45,1.775 h0.75
  text "'.Designator'" at -2,0 h0.75
M16-Top Courtyard:
  lines w0.01: -3.3,-4.3 3.3,-4.3 3.3,4.3 -3.3,4.3 -3.3,-4.3
3D body: height 0.36, standoff -0.04, extent 1.801,-2.197 2.2,-1.803
3D body: height 0.36, standoff -0.04, extent 0.801,-2.197 1.2,-1.803
3D body: height 0.36, standoff -0.04, extent -0.199,-2.197 0.2,-1.803
3D body: height 0.36, standoff -0.04, extent -1.199,-2.197 -0.8,-1.803
3D body: height 0.36, standoff -0.04, extent -2.199,-2.197 -1.8,-1.803
3D body: height 0.36, standoff -0.04, extent 1.801,-1.197 2.2,-0.803
3D body: height 0.36, standoff -0.04, extent 0.801,-1.197 1.2,-0.803
3D body: height 0.36, standoff -0.04, extent -0.199,-1.197 0.2,-0.803
3D body: height 0.36, standoff -0.04, extent -1.199,-1.197 -0.8,-0.803
3D body: height 0.36, standoff -0.04, extent -2.199,-1.197 -1.8,-0.803
3D body: height 0.36, standoff -0.04, extent 1.801,-0.197 2.2,0.197
3D body: height 0.36, standoff -0.04, extent 0.801,-0.197 1.2,0.197
3D body: height 0.36, standoff -0.04, extent -0.199,-0.197 0.2,0.197
3D body: height 0.36, standoff -0.04, extent -1.199,-0.197 -0.8,0.197
3D body: height 0.36, standoff -0.04, extent -2.199,-0.197 -1.8,0.197
3D body: height 0.36, standoff -0.04, extent 1.801,0.803 2.2,1.197
3D body: height 0.36, standoff -0.04, extent 0.801,0.803 1.2,1.197
3D body: height 0.36, standoff -0.04, extent -0.199,0.803 0.2,1.197
3D body: height 0.36, standoff -0.04, extent -1.199,0.803 -0.8,1.197
3D body: height 0.36, standoff -0.04, extent -2.199,0.803 -1.8,1.197
3D body: height 0.36, standoff -0.04, extent 1.801,1.803 2.2,2.197
3D body: height 0.36, standoff -0.04, extent 0.801,1.803 1.2,2.197
3D body: height 0.36, standoff -0.04, extent -0.199,1.803 0.2,2.197
3D body: height 0.36, standoff -0.04, extent -1.199,1.803 -0.8,2.197
3D body: height 1.2, standoff 0.3, extent -3.055,-4.055 3.055,4.055
3D body: height 1.21, standoff 1.2, extent -2.623,3.026 -2.025,3.625

## ICC_MINI-BGA48_6X8_P075 [mm]
height 1.2
pads (48):
  round 0.32 smd mask+0.05: A1(-1.875,2.625) A2(-1.125,2.625) A3(-0.375,2.625) A4(0.375,2.625) A5(1.125,2.625) A6(1.875,2.625) B1(-1.875,1.875) B2(-1.125,1.875) B3(-0.375,1.875) B4(0.375,1.875) B5(1.125,1.875) B6(1.875,1.875) C1(-1.875,1.125) C2(-1.125,1.125) C3(-0.375,1.125) C4(0.375,1.125) C5(1.125,1.125) C6(1.875,1.125) D1(-1.875,0.375) D2(-1.125,0.375) D3(-0.375,0.375) D4(0.375,0.375) D5(1.125,0.375) D6(1.875,0.375) E1(-1.875,-0.375) E2(-1.125,-0.375) E3(-0.375,-0.375) E4(0.375,-0.375) E5(1.125,-0.375) E6(1.875,-0.375) F1(-1.875,-1.125) F2(-1.125,-1.125) F3(-0.375,-1.125) F4(0.375,-1.125) F5(1.125,-1.125) F6(1.875,-1.125) G1(-1.875,-1.875) G2(-1.125,-1.875) G3(-0.375,-1.875) G4(0.375,-1.875) G5(1.125,-1.875) G6(1.875,-1.875) H1(-1.875,-2.625) H2(-1.125,-2.625) H3(-0.375,-2.625) H4(0.375,-2.625) H5(1.125,-2.625) H6(1.875,-2.625)
Top Overlay:
  lines w0.12: -3.175,3.75 -3.175,4.175 -2.75,4.175 ; -3.05,-4.05 -3.05,4.05 3.05,4.05 3.05,-4.05 -3.05,-4.05
  text "A1" at -2.925,3.15 h1.2
M14-Top Assembly:
  circle w0.01: c-1.875,2.625 r0.3
  lines w0.01: -3.05,-4.05 3.05,-4.05 3.05,4.05 -3.05,4.05 -3.05,-4.05 ; -2.875,3.375 -2.875,3.5 -2.875,3.875 -2.375,3.875 -2.875,3.375
  text "'.Designator'" at -2,-0.5 h0.75
  text "A1" at -2.225,2.975 h0.75
M16-Top Courtyard:
  lines w0.01: -3.3,-4.3 3.3,-4.3 3.3,4.3 -3.3,4.3 -3.3,-4.3
3D body: height 1.2, standoff 0, extent -3.055,-4.055 3.055,4.055
3D body "MINI-BGA48_6X8.STEP": height 1.2, standoff 0, extent -3,-4 3,4

## ICC_MINI-BGA48_9X11_P075 [mm] "IPC"
height 1.2
pads (48):
  round 0.28 smd mask+0.05: A1(-1.875,2.625) A2(-1.125,2.625) A3(-0.375,2.625) A4(0.375,2.625) A5(1.125,2.625) A6(1.875,2.625) B1(-1.875,1.875) B2(-1.125,1.875) B3(-0.375,1.875) B4(0.375,1.875) B5(1.125,1.875) B6(1.875,1.875) C1(-1.875,1.125) C2(-1.125,1.125) C3(-0.375,1.125) C4(0.375,1.125) C5(1.125,1.125) C6(1.875,1.125) D1(-1.875,0.375) D2(-1.125,0.375) D3(-0.375,0.375) D4(0.375,0.375) D5(1.125,0.375) D6(1.875,0.375) E1(-1.875,-0.375) E2(-1.125,-0.375) E3(-0.375,-0.375) E4(0.375,-0.375) E5(1.125,-0.375) E6(1.875,-0.375) F1(-1.875,-1.125) F2(-1.125,-1.125) F3(-0.375,-1.125) F4(0.375,-1.125) F5(1.125,-1.125) F6(1.875,-1.125) G1(-1.875,-1.875) G2(-1.125,-1.875) G3(-0.375,-1.875) G4(0.375,-1.875) G5(1.125,-1.875) G6(1.875,-1.875) H1(-1.875,-2.625) H2(-1.125,-2.625) H3(-0.375,-2.625) H4(0.375,-2.625) H5(1.125,-2.625) H6(1.875,-2.625)
Top Overlay:
  circle w0.12: c-4,5 r0.3
  lines w0.12: -4.7,5 -4.7,5.7 -4,5.7 ; -4.55,-5.55 -4.55,5.55 4.55,5.55 4.55,-5.55 -4.55,-5.55
  text "A1" at -2.575,2.95 h1.5
M14-Top Assembly:
  circle w0.01: c-1.125,-2.625 r0.175
  circle w0.01: c-1.875,-2.625 r0.175
  circle w0.01: c-0.375,-2.625 r0.175
  circle w0.01: c0.375,-2.625 r0.175
  circle w0.01: c1.125,-2.625 r0.175
  circle w0.01: c1.875,-2.625 r0.175
  circle w0.01: c-1.125,-1.875 r0.175
  circle w0.01: c-1.875,-1.875 r0.175
  circle w0.01: c-0.375,-1.875 r0.175
  circle w0.01: c0.375,-1.875 r0.175
  circle w0.01: c1.125,-1.875 r0.175
  circle w0.01: c1.875,-1.875 r0.175
  circle w0.01: c-1.125,-1.125 r0.175
  circle w0.01: c-1.875,-1.125 r0.175
  circle w0.01: c-0.375,-1.125 r0.175
  circle w0.01: c0.375,-1.125 r0.175
  circle w0.01: c1.125,-1.125 r0.175
  circle w0.01: c1.875,-1.125 r0.175
  circle w0.01: c-1.125,-0.375 r0.175
  circle w0.01: c-1.875,-0.375 r0.175
  circle w0.01: c-0.375,-0.375 r0.175
  circle w0.01: c0.375,-0.375 r0.175
  circle w0.01: c1.125,-0.375 r0.175
  circle w0.01: c1.875,-0.375 r0.175
  circle w0.01: c-1.125,0.375 r0.175
  circle w0.01: c-1.875,0.375 r0.175
  circle w0.01: c-0.375,0.375 r0.175
  circle w0.01: c0.375,0.375 r0.175
  circle w0.01: c1.125,0.375 r0.175
  circle w0.01: c1.875,0.375 r0.175
  circle w0.01: c-1.125,1.125 r0.175
  circle w0.01: c-1.875,1.125 r0.175
  circle w0.01: c-0.375,1.125 r0.175
  circle w0.01: c0.375,1.125 r0.175
  circle w0.01: c1.125,1.125 r0.175
  circle w0.01: c1.875,1.125 r0.175
  circle w0.01: c-1.125,1.875 r0.175
  circle w0.01: c-1.875,1.875 r0.175
  circle w0.01: c-0.375,1.875 r0.175
  circle w0.01: c0.375,1.875 r0.175
  circle w0.01: c1.125,1.875 r0.175
  circle w0.01: c1.875,1.875 r0.175
  circle w0.01: c1.875,2.625 r0.175
  circle w0.01: c1.125,2.625 r0.175
  circle w0.01: c0.375,2.625 r0.175
  circle w0.01: c-0.375,2.625 r0.175
  circle w0.01: c-4,5 r0.3
  circle w0.01: c-1.875,2.625 r0.175
  circle w0.01: c-1.125,2.625 r0.175
  lines w0.01: -4.55,-5.55 4.55,-5.55 4.55,5.55 -4.55,5.55 -4.55,-5.55
  text "'.Designator'" at -2,-0.5 h0.75
  text "A1" at -2.125,2.475 h0.5
M16-Top Courtyard:
  lines w0.01: -4.8,-5.8 4.8,-5.8 4.8,5.8 -4.8,5.8 -4.8,-5.8
3D body: height 0.31, standoff -0.05, extent -2.041,2.458 -1.7,2.792
3D body: height 1.21, standoff 1.2, extent -4.248,4.75 -3.75,5.25
3D body: height 1.2, standoff 0.25, extent -4.55,-5.55 4.55,5.55
3D body: height 0.31, standoff -0.05, extent -1.291,2.458 -0.95,2.792
3D body: height 0.31, standoff -0.05, extent -0.541,2.458 -0.2,2.792
3D body: height 0.31, standoff -0.05, extent 0.209,2.458 0.55,2.792
3D body: height 0.31, standoff -0.05, extent 0.959,2.458 1.3,2.792
3D body: height 0.31, standoff -0.05, extent 1.709,2.458 2.05,2.792
3D body: height 0.31, standoff -0.05, extent 1.709,1.708 2.05,2.042
3D body: height 0.31, standoff -0.05, extent 0.959,1.708 1.3,2.042
3D body: height 0.31, standoff -0.05, extent 0.209,1.708 0.55,2.042
3D body: height 0.31, standoff -0.05, extent -0.541,1.708 -0.2,2.042
3D body: height 0.31, standoff -0.05, extent -1.291,1.708 -0.95,2.042
3D body: height 0.31, standoff -0.05, extent -2.041,1.708 -1.7,2.042
3D body: height 0.31, standoff -0.05, extent 1.709,0.958 2.05,1.292
3D body: height 0.31, standoff -0.05, extent 0.959,0.958 1.3,1.292
3D body: height 0.31, standoff -0.05, extent 0.209,0.958 0.55,1.292
3D body: height 0.31, standoff -0.05, extent -0.541,0.958 -0.2,1.292
3D body: height 0.31, standoff -0.05, extent -1.291,0.958 -0.95,1.292
3D body: height 0.31, standoff -0.05, extent -2.041,0.958 -1.7,1.292
3D body: height 0.31, standoff -0.05, extent 1.709,0.208 2.05,0.542
3D body: height 0.31, standoff -0.05, extent 0.959,0.208 1.3,0.542
3D body: height 0.31, standoff -0.05, extent 0.209,0.208 0.55,0.542
3D body: height 0.31, standoff -0.05, extent -0.541,0.208 -0.2,0.542
3D body: height 0.31, standoff -0.05, extent -1.291,0.208 -0.95,0.542
3D body: height 0.31, standoff -0.05, extent -2.041,0.208 -1.7,0.542
3D body: height 0.31, standoff -0.05, extent 1.709,-0.542 2.05,-0.208
3D body: height 0.31, standoff -0.05, extent 0.959,-0.542 1.3,-0.208
3D body: height 0.31, standoff -0.05, extent 0.209,-0.542 0.55,-0.208
3D body: height 0.31, standoff -0.05, extent -0.541,-0.542 -0.2,-0.208
3D body: height 0.31, standoff -0.05, extent -1.291,-0.542 -0.95,-0.208
3D body: height 0.31, standoff -0.05, extent -2.041,-0.542 -1.7,-0.208
3D body: height 0.31, standoff -0.05, extent 1.709,-1.292 2.05,-0.958
3D body: height 0.31, standoff -0.05, extent 0.959,-1.292 1.3,-0.958
3D body: height 0.31, standoff -0.05, extent 0.209,-1.292 0.55,-0.958
3D body: height 0.31, standoff -0.05, extent -0.541,-1.292 -0.2,-0.958
3D body: height 0.31, standoff -0.05, extent -1.291,-1.292 -0.95,-0.958
3D body: height 0.31, standoff -0.05, extent -2.041,-1.292 -1.7,-0.958
3D body: height 0.31, standoff -0.05, extent 1.709,-2.042 2.05,-1.708
3D body: height 0.31, standoff -0.05, extent 0.959,-2.042 1.3,-1.708
3D body: height 0.31, standoff -0.05, extent 0.209,-2.042 0.55,-1.708
3D body: height 0.31, standoff -0.05, extent -0.541,-2.042 -0.2,-1.708
3D body: height 0.31, standoff -0.05, extent -1.291,-2.042 -0.95,-1.708
3D body: height 0.31, standoff -0.05, extent -2.041,-2.042 -1.7,-1.708
3D body: height 0.31, standoff -0.05, extent 1.709,-2.792 2.05,-2.458
3D body: height 0.31, standoff -0.05, extent 0.959,-2.792 1.3,-2.458
3D body: height 0.31, standoff -0.05, extent 0.209,-2.792 0.55,-2.458
3D body: height 0.31, standoff -0.05, extent -0.541,-2.792 -0.2,-2.458
3D body: height 0.31, standoff -0.05, extent -1.291,-2.792 -0.95,-2.458
3D body: height 0.31, standoff -0.05, extent -2.041,-2.792 -1.7,-2.458

## ICC_MINISO8_3X3_P065 [mm]
height 1.1
pads (8):
  rect 0.4x1.4 smd mask+0.05: 1(0.975,2.125) 2(0.325,2.125) 3(-0.325,2.125) 4(-0.975,2.125) 5(-0.975,-2.125) 6(-0.325,-2.125) 7(0.325,-2.125) 8(0.975,-2.125)
Top Overlay:
  circle w0.12: c1,1 r0.25
  lines w0.12: -1.3,-1.55 -1.6,-1.55 -1.6,1.55 -1.3,1.55 ; 1.3,-1.55 1.6,-1.55 1.6,1.55 1.3,1.55
  text "1" at 1.3,1.675 h1.5
M14-Top Assembly:
  circle w0.01: c1,1 r0.25
  lines w0.01: -1.1,-1.55 -1.1,-2.575 -0.85,-2.575 -0.85,-1.55 ; -1.1,1.55 -1.1,2.575 -0.85,2.575 -0.85,1.55 ; -0.45,-1.55 -0.45,-2.575 -0.2,-2.575 -0.2,-1.55 ; -0.45,1.55 -0.45,2.575 -0.2,2.575 -0.2,1.55 ; 0.2,-1.55 0.2,-2.575 0.45,-2.575 0.45,-1.55 ; 0.2,1.55 0.2,2.575 0.45,2.575 0.45,1.55 ; 0.85,-1.55 0.85,-2.575 1.1,-2.575 1.1,-1.55 ; 0.85,1.55 0.85,2.575 1.1,2.575 1.1,1.55 ; -1.6,-1.55 1.6,-1.55 1.6,1.55 -1.6,1.55 -1.6,-1.55
  text "8" at 0.775,-2.3 h1
  text "5" at -1.2,-2.3 h1
  text "4" at -1.175,1.65 h1
  text "1" at 0.875,1.65 h1
  text "'.Designator'" at -2,-0.5 h0.75
M16-Top Courtyard:
  lines w0.01: -1.8,-2.975 1.8,-2.975 1.8,2.975 -1.8,2.975 -1.8,-2.975
3D body: height 1.1, standoff 0, extent -1.599,-1.549 1.599,1.549
3D body: height 1.11, standoff 1.1, extent 0.802,0.801 1.2,1.2
3D body: height 0.2, standoff 0, extent -1.1,1.55 -0.85,2.575
3D body: height 0.2, standoff 0, extent -0.45,1.55 -0.2,2.575
3D body: height 0.2, standoff 0, extent 0.2,1.55 0.45,2.575
3D body: height 0.2, standoff 0, extent 0.85,1.55 1.1,2.575
3D body: height 0.2, standoff 0, extent -1.1,-2.575 -0.85,-1.55
3D body: height 0.2, standoff 0, extent -0.45,-2.575 -0.2,-1.55
3D body: height 0.2, standoff 0, extent 0.2,-2.575 0.45,-1.55
3D body: height 0.2, standoff 0, extent 0.85,-2.575 1.1,-1.55

## ICC_MMM168_H1P9 [mm]
height 1.19
pads (4):
  rect 0.9x1.3 smd mask+0.05: 1(0.915,1.1) 2(0.915,-1.1) 4(-0.99,1.1)
  rect 1.2x1.3 smd mask+0.05: 3(-0.79,-1.1)
Top Overlay:
  lines w0.12: -1.525,-0.325 -1.525,0.275 ; -0.375,0.7 0.275,0.7 ; -0.025,-0.7 0.3,-0.7 ; 1.525,-0.3 1.525,0.3
  text "1" at 1.475,1.125 h1.5
M14-Top Assembly:
  circle w0.01: c1.25,0.451 r0.125
  lines w0.01: -1.255,0.7 -1.255,1.32 -0.725,1.32 -0.725,0.7 ; -1.208,-0.7 -1.208,-1.32 -0.373,-1.32 -0.373,-0.7 ; 0.65,-0.7 0.65,-1.32 1.18,-1.32 1.18,-0.7 ; 0.65,0.7 0.65,1.32 1.18,1.32 1.18,0.7 ; -1.525,-0.7 1.525,-0.7 1.525,0.7 -1.525,0.7 -1.525,-0.7
  text "'.Designator'" at -2,-0.5 h0.75
M16-Top Courtyard:
  lines w0.01: -1.775,-1.9 -1.775,1.9 1.775,1.9 1.775,-1.9 -1.775,-1.9
3D body "User Library-LAT-8.STEP": height 1.13, standoff 0, extent -1.429,-1.188 1.429,1.188

## ICC_MSOP8_RM-8_MO-187-AA_3X3_P065 [mm] "MCD-01434"
height 1.1
pads (8):
  rect 0.45x1.45 smd mask+0.05: 1(-0.975,-2.2) 2(-0.325,-2.2) 3(0.325,-2.2) 4(0.975,-2.2) 5(0.975,2.2) 6(0.325,2.2) 7(-0.325,2.2) 8(-0.975,2.2)
Top Overlay:
  circle w0.12: c-1.125,-1.125 r0.225
  lines w0.12: -1.325,-1.55 -1.55,-1.55 -1.55,1.55 -1.325,1.55 ; 1.325,-1.55 1.55,-1.55 1.55,1.55 1.325,1.55
  text "1" at -1.675,-2.7 h1.5
M14-Top Assembly:
  circle w0.01: c-1.125,-1.125 r0.25
  lines w0.01: -1.175,-1.55 -1.175,-2.55 -0.775,-2.55 -0.775,-1.55 ; -1.175,1.55 -1.175,2.55 -0.775,2.55 -0.775,1.55 ; -0.525,-1.55 -0.525,-2.55 -0.125,-2.55 -0.125,-1.55 ; -0.525,1.55 -0.525,2.55 -0.125,2.55 -0.125,1.55 ; 0.125,-1.55 0.125,-2.55 0.525,-2.55 0.525,-1.55 ; 0.125,1.55 0.125,2.55 0.525,2.55 0.525,1.55 ; 0.775,-1.55 0.775,-2.55 1.175,-2.55 1.175,-1.55 ; 0.775,1.55 0.775,2.55 1.175,2.55 1.175,1.55 ; -1.55,-1.55 -1.55,1.55 1.55,1.55 1.55,-1.55 -1.55,-1.55
  text "'.Designator'" at -2,-0.5 h0.75
  text "5" at 0.775,1.725 h1
  text "8" at -1.2,1.725 h1
  text "4" at 0.75,-2.375 h1
  text "1" at -1.1,-2.4 h1
M16-Top Courtyard:
  lines w0.01: -1.75,-3.075 1.75,-3.075 1.75,3.075 -1.75,3.075 -1.75,-3.075
3D body "VSSOP8-3X3_P065.STEP": height 0.96, standoff 0, extent -1.5,-2.45 1.5,2.45
3D body: height 1.1, standoff 0, extent -1.55,-1.55 1.55,1.55
3D body: height 1.11, standoff 1.1, extent -1.373,-1.374 -0.875,-0.875

## ICC_MSOP10-EPAD_3X3_P050 [mm]
height 1.1
pads (11):
  rect 0.3x1.35 smd paste+0 mask+0.05: 1(-1,-2.125) 2(-0.5,-2.125) 3(0,-2.125) 4(0.5,-2.125) 5(1,-2.125) 6(1,2.125) 7(0.5,2.125) 8(0,2.125) 9(-0.5,2.125) 10(-1,2.125)
  rect 2.3x2.5 smd paste+0 mask+0.05: 11(0,0)
Top Overlay:
  circle w0.12: c-1.325,-1.325 r0.1
  lines w0.12: -1.275,-1.55 -1.55,-1.55 -1.55,1.55 -1.275,1.55 ; 1.275,-1.55 1.55,-1.55 1.55,1.55 1.275,1.55
  text "1" at -1.625,-2.65 h1.5
M14-Top Assembly:
  circle w0.01: c-1.3,-1.3 r0.175
  lines w0.01: -1.125,-1.55 -1.125,-2.5 -0.875,-2.5 -0.875,-1.55 ; -1.125,1.55 -1.125,2.5 -0.875,2.5 -0.875,1.55 ; -0.625,-1.55 -0.625,-2.5 -0.375,-2.5 -0.375,-1.55 ; -0.625,1.55 -0.625,2.5 -0.375,2.5 -0.375,1.55 ; -0.125,-1.55 -0.125,-2.5 0.125,-2.5 0.125,-1.55 ; -0.125,1.55 -0.125,2.5 0.125,2.5 0.125,1.55 ; 0.375,-1.55 0.375,-2.5 0.625,-2.5 0.625,-1.55 ; 0.375,1.55 0.375,2.5 0.625,2.5 0.625,1.55 ; 0.875,-1.55 0.875,-2.5 1.125,-2.5 1.125,-1.55 ; 0.875,1.55 0.875,2.5 1.125,2.5 1.125,1.55 ; -1.55,-1.55 1.55,-1.55 1.55,1.55 -1.55,1.55 -1.55,-1.55 ; -0.85,-0.95 0.85,-0.95 0.85,0.95 -0.85,0.95 -0.85,-0.95
  text "1" at -1.125,-2.35 h1
  text "5" at 0.8,-2.35 h1
  text "6" at 0.8,1.75 h1
  text "10" at -1.425,1.75 h1
  text "'.Designator'" at -2,-0.5 h0.75
M16-Top Courtyard:
  lines w0.01: -1.75,-2.95 -1.75,2.95 1.75,2.95 1.75,-2.95 -1.75,-2.95
3D body: height 1.1, standoff 0, extent -1.549,-1.549 1.549,1.549
3D body "MSOP10-EPAD_3X3_P050.STEP": height 1.07, standoff -0.03, extent -1.55,-2.518 1.55,2.518

## ICC_MSOP10_3X3_P050 [mm] "MCD-04304"
height 1.1
pads (10):
  rect 0.3x1.35 smd paste+0 mask+0.05: 1(-1,-2.125) 2(-0.5,-2.125) 3(0,-2.125) 4(0.5,-2.125) 5(1,-2.125) 6(1,2.125) 7(0.5,2.125) 8(0,2.125) 9(-0.5,2.125) 10(-1,2.125)
Top Overlay:
  circle w0.12: c-1.325,-1.325 r0.1
  lines w0.12: -1.275,-1.55 -1.55,-1.55 -1.55,1.55 -1.275,1.55 ; 1.275,-1.55 1.55,-1.55 1.55,1.55 1.275,1.55
  text "1" at -1.625,-2.65 h1.5
M14-Top Assembly:
  circle w0.01: c-1.3,-1.3 r0.175
  lines w0.01: -1.125,-1.55 -1.125,-2.5 -0.875,-2.5 -0.875,-1.55 ; -1.125,1.55 -1.125,2.5 -0.875,2.5 -0.875,1.55 ; -0.625,-1.55 -0.625,-2.5 -0.375,-2.5 -0.375,-1.55 ; -0.625,1.55 -0.625,2.5 -0.375,2.5 -0.375,1.55 ; -0.125,-1.55 -0.125,-2.5 0.125,-2.5 0.125,-1.55 ; -0.125,1.55 -0.125,2.5 0.125,2.5 0.125,1.55 ; 0.375,-1.55 0.375,-2.5 0.625,-2.5 0.625,-1.55 ; 0.375,1.55 0.375,2.5 0.625,2.5 0.625,1.55 ; 0.875,-1.55 0.875,-2.5 1.125,-2.5 1.125,-1.55 ; 0.875,1.55 0.875,2.5 1.125,2.5 1.125,1.55 ; -1.55,-1.55 1.55,-1.55 1.55,1.55 -1.55,1.55 -1.55,-1.55
  text "1" at -1.125,-2.35 h1
  text "5" at 0.8,-2.35 h1
  text "6" at 0.8,1.75 h1
  text "10" at -1.425,1.75 h1
  text "'.Designator'" at -2,-0.5 h0.75
M16-Top Courtyard:
  lines w0.01: -1.75,-2.95 -1.75,2.95 1.75,2.95 1.75,-2.95 -1.75,-2.95
3D body "User Library-MSOP-10-1.STEP": height 1.05, standoff 0, extent -1.5,-2.514 1.5,2.514

## ICC_MURATA_LFD182G45DCJD247_1P6x0P8_P050 [mm] "MCD-03021"
height 0.7
pads (9):
  round 0 hole 0.3 unplated mask+0: 0(-0.7,-1) 0(0,1) 0(0.7,-1)
  rect 0.25x0.5 smd mask+0.05: 1(0.5,0.45) 2(0,0.45) 3(-0.5,0.45) 5(-0.5,-0.45) 6(0,-0.45) 7(0.5,-0.45)
Top Overlay:
  lines w0.1: -0.85,-0.45 -0.85,0.45 ; 0.85,-0.45 0.85,0.45
  text "1" at 0.725,0.6 h1.2
M14-Top Assembly:
  lines w0.01: -0.85,-0.45 -0.85,0.45 0.85,0.45 0.85,-0.45 -0.85,-0.45 ; -0.65,-0.45 -0.35,-0.45 -0.35,-0.2 -0.65,-0.2 -0.65,-0.45 ; -0.65,0.2 -0.65,0.45 -0.35,0.45 -0.35,0.2 -0.65,0.2 ; -0.15,-0.45 0.15,-0.45 0.15,-0.2 -0.15,-0.2 -0.15,-0.45 ; -0.15,0.2 -0.15,0.45 0.15,0.45 0.15,0.2 -0.15,0.2 ; 0.2,-0.075 0.2,0.075 0.5,0.075 0.5,-0.075 0.2,-0.075 ; 0.35,-0.45 0.65,-0.45 0.65,-0.2 0.35,-0.2 0.35,-0.45 ; 0.35,0.2 0.35,0.45 0.65,0.45 0.65,0.2 0.35,0.2
  text "5" at -0.6,-0.45 h0.5
  text "6" at -0.1,-0.45 h0.5
  text "7" at 0.425,-0.45 h0.5
  text "3" at -0.6,0.2 h0.5
  text "2" at -0.1,0.2 h0.5
  text "1" at 0.425,0.2 h0.5
  text "'.Designator'" at -2,-0.5 h0.75
M16-Top Courtyard:
  lines w0.01: -1.1,-1.25 -1.1,1.25 1.1,1.25 1.1,-1.25 -1.1,-1.25
3D body: height 0.7, standoff 0, extent -0.85,-0.45 0.85,0.45

## ICC_ON-SEMI_ODCSP4_LV0104CS-D [mm] "MCD-01807"
height 0.68
pads (4):
  round 0.25 smd mask+0.05: 1(-0.25,-0.25) 2(0.25,-0.25) 3(0.25,0.25) 4(-0.25,0.25)
Top Overlay:
  lines w0.12: -0.575,-0.375 -0.375,-0.575 ; -0.575,-0.575 -0.575,0.575 0.575,0.575 0.575,-0.575 -0.575,-0.575
  text "1" at -1.2,-1.175 h1.5
M14-Top Assembly:
  circle w0.01: c0.25,0.25 r0.125
  circle w0.01: c-0.25,-0.25 r0.125
  circle w0.01: c0.25,-0.25 r0.125
  circle w0.01: c-0.25,0.25 r0.125
  lines w0.01: -0.575,-0.25 -0.25,-0.575 ; -0.575,-0.575 -0.575,0.575 0.575,0.575 0.575,-0.575 -0.575,-0.575
  text "'.Designator'" at -2,-0.5 h0.75
M16-Top Courtyard:
  lines w0.01: -0.775,-0.775 -0.775,0.775 0.775,0.775 0.775,-0.775 -0.775,-0.775
3D body: height 0.68, standoff 0.1, extent -0.575,-0.575 0.575,0.575
3D body: height 0.1, standoff 0, extent -0.374,0.125 -0.125,0.375
3D body: height 0.1, standoff 0, extent 0.126,0.125 0.375,0.375
3D body: height 0.1, standoff 0, extent -0.374,-0.375 -0.125,-0.125
3D body: height 0.1, standoff 0, extent 0.126,-0.375 0.375,-0.125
